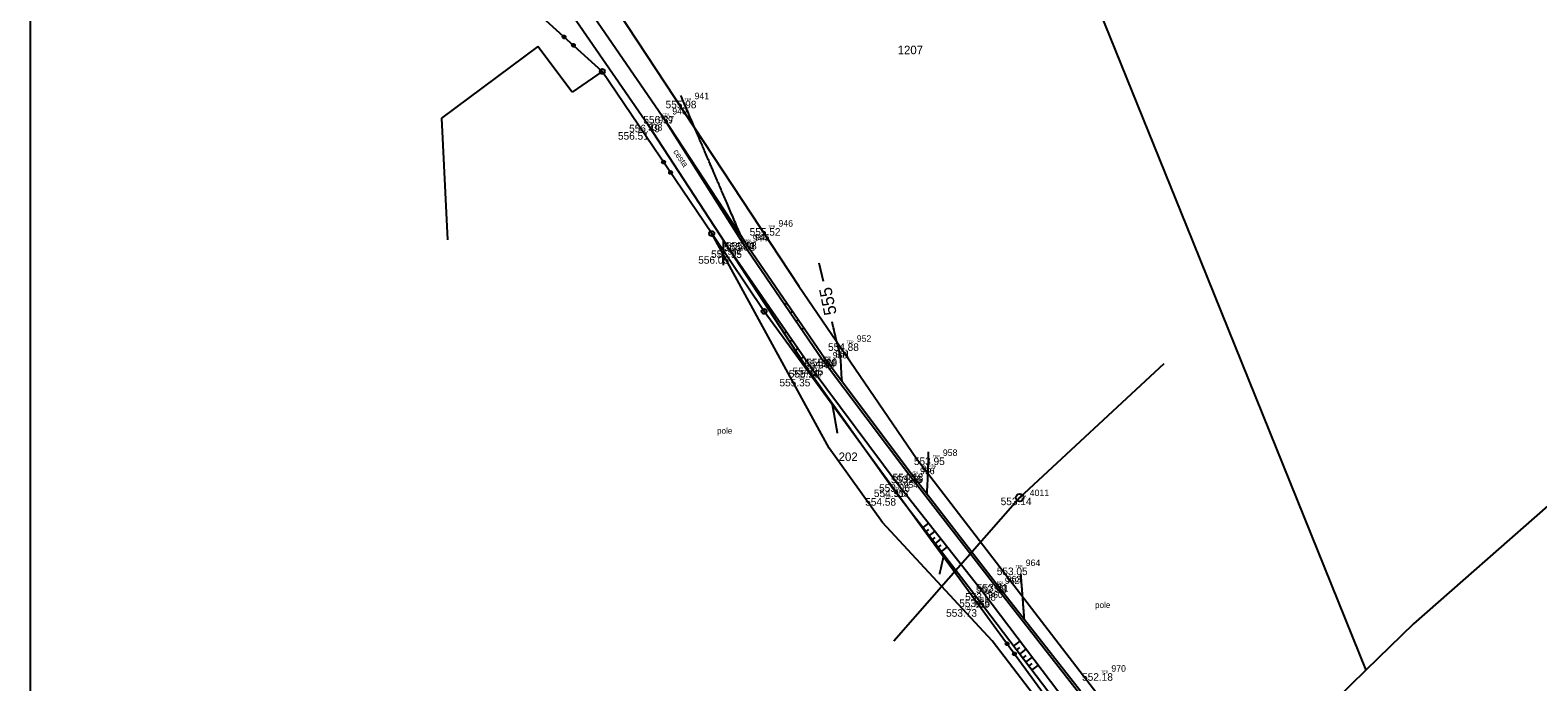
# Model space of a CAD drawing. Extents: x -604848 to -603227, y -1111879 to -1109838.
# Drawn here: x -604847.7 to -604547.7, y -1111483.6 to -1111354 of the extents above; entities that cross this region are included whole.
import ezdxf

# ---------------------------------------------------------------- set-up
doc = ezdxf.new("R2010")
doc.units = 0
for name, color, linetype in [('1', 7, 'Continuous'), ('10', 7, 'Continuous'), ('14', 7, 'Continuous'), ('18', 7, 'Continuous'), ('19', 7, 'Continuous'), ('20', 7, 'Continuous'), ('28', 7, 'Continuous'), ('4', 7, 'Continuous'), ('5', 7, 'Continuous'), ('62', 7, 'Continuous'), ('7', 7, 'Continuous'), ('8', 7, 'Continuous'), ('9', 7, 'Continuous'), ('Default', 7, 'Continuous')]:
    doc.layers.add(name, color=color, linetype=linetype)

# ---------------------------------------------------------------- blocks, each defined once
blk = doc.blocks.new('Z105')
at = {"layer": '28'}
for radius in [0.5, 0.01]:
    blk.add_circle((0, 0), radius, dxfattribs=at)
blk = doc.blocks.new('POINT_DISPLAY')
at = {"layer": 'Default'}
blk.add_line((0, 0), (0, 0), dxfattribs=at)
blk = doc.blocks.new('Z101')
at = {"layer": '28'}
for radius in [0.75, 0.01]:
    blk.add_circle((0, 0), radius, dxfattribs=at)
blk = doc.blocks.new('Z206')
at = {"layer": '62'}
for p, q in [((-1.7, 0.1), (-1.5, 0.3)), ((-1.7, -0.1), (-1.7, 0.1)), ((-1.6, 0.1), (-1.6, -0.1)), ((-1.5, 0.3), (-1.3, 0.3)), ((-1.5, -0.2), (-1.5, 0.2)), ((-1.5, 0.2), (-1.3, 0.2)), ((-1.4, 0.2), (-1.4, -0.2)), ((-1.3, 0.3), (-1.1, 0.1)), ((-1.3, 0.2), (-1.3, -0.2)), ((-1.2, -0.1), (-1.2, 0.1)), ((-1.1, 0.1), (-1.1, -0.1)), ((0.8, 0.1), (1, 0.3)), ((0.8, -0.1), (0.8, 0.1)), ((0.9, 0.1), (0.9, -0.1)), ((1, 0.3), (1.2, 0.3)), ((1, -0.2), (1, 0.2)), ((1, 0.2), (1.2, 0.2)), ((1.1, 0.2), (1.1, -0.2)), ((1.2, 0.3), (1.4, 0.1)), ((1.2, 0.2), (1.2, -0.2)), ((1.3, -0.1), (1.3, 0.1)), ((1.4, 0.1), (1.4, -0.1)), ((-1.5, -0.3), (-1.7, -0.1)), ((-1.6, -0.1), (-1.5, -0.2)), ((-1.3, -0.3), (-1.5, -0.3)), ((-1.1, -0.1), (-1.3, -0.3)), ((-1.3, -0.2), (-1.2, -0.1)), ((1, -0.3), (0.8, -0.1)), ((0.9, -0.1), (1, -0.2)), ((1.2, -0.3), (1, -0.3)), ((1.4, -0.1), (1.2, -0.3)), ((1.2, -0.2), (1.3, -0.1))]:
    blk.add_line(p, q, dxfattribs=at)

msp = doc.modelspace()

# ---------------------------------------------------------------- linework, layer by layer
at = {"layer": '1'}
for p, q in [((-604684.78, -1111226.85), (-604617.61, -1111392.95)), ((-604732.69, -1111347.27), (-604694.74, -1111404.88)), ((-604746.66, -1111357.26), (-604765.86, -1111371.5)), ((-604739.83, -1111366.3), (-604746.66, -1111357.26)), ((-604733.84, -1111362.2), (-604739.83, -1111366.3)), ((-604765.86, -1111371.5), (-604764.64, -1111395.7)), ((-604688.69, -1111437.09), (-604712.07, -1111394.44)), ((-604617.61, -1111392.95), (-604581.91, -1111481.23)), ((-604694.74, -1111404.88), (-604671.29, -1111439.17)), ((-604678.05, -1111451.87), (-604688.69, -1111437.09)), ((-604671.29, -1111439.17), (-604631.49, -1111490.96)), ((-604545.66, -1111448.58), (-604572.43, -1111472.02)), ((-604656.29, -1111475.4), (-604678.05, -1111451.87)), ((-604572.43, -1111472.02), (-604581.91, -1111481.23)), ((-604624.3, -1111517.02), (-604656.29, -1111475.4)), ((-604581.91, -1111481.23), (-604592.51, -1111491.58))]:
    msp.add_line(p, q, dxfattribs=at)
msp.add_lwpolyline([(-604253.71, -1111878.79), (-604253.71, -1111038.79), (-604847.71, -1111038.79), (-604847.71, -1111878.79), (-604253.71, -1111878.79)], dxfattribs=at)
at = {"layer": '10'}
for p, q in [((-604721.91, -1111371.06), (-604705.47, -1111396.11)), ((-604692.86, -1111421.57), (-604708.43, -1111397.78)), ((-604705.47, -1111396.11), (-604689.5, -1111419.35)), ((-604689.5, -1111419.35), (-604672.3, -1111442.2)), ((-604675.9, -1111445.34), (-604692.86, -1111421.57)), ((-604672.3, -1111442.2), (-604655.38, -1111464.11)), ((-604659.04, -1111467.21), (-604675.9, -1111445.34)), ((-604655.38, -1111464.11), (-604638.7, -1111485.39)), ((-604642.45, -1111489.02), (-604659.04, -1111467.21))]:
    msp.add_line(p, q, dxfattribs=at)
at = {"layer": '4'}
for p, q in [((-604740.23, -1111350.33), (-604724.71, -1111372.8)), ((-604737.6, -1111348.29), (-604721.91, -1111371.06)), ((-604733.84, -1111362.2), (-604745.77, -1111351.46)), ((-604712.07, -1111394.44), (-604733.84, -1111362.2)), ((-604721.91, -1111371.06), (-604705.89, -1111396.34)), ((-604708.43, -1111397.78), (-604724.71, -1111372.8)), ((-604701.64, -1111409.91), (-604712.07, -1111394.44)), ((-604692.25, -1111421.11), (-604708.43, -1111397.78)), ((-604705.89, -1111396.34), (-604689.99, -1111419.58)), ((-604639.06, -1111495.46), (-604701.64, -1111409.91)), ((-604692.25, -1111421.11), (-604674.94, -1111444.31)), ((-604672.61, -1111442.59), (-604689.99, -1111419.58)), ((-604655.73, -1111464.43), (-604672.61, -1111442.59)), ((-604674.94, -1111444.31), (-604657.89, -1111465.95)), ((-604657.89, -1111465.95), (-604641.32, -1111487.8)), ((-604639.07, -1111485.72), (-604655.73, -1111464.43))]:
    msp.add_line(p, q, dxfattribs=at)
at = {"layer": '5'}
for q in [(-604622.03, -1111420.28), (-604675.85, -1111475.52)]:
    msp.add_line((-604650.78, -1111446.95), q, dxfattribs=at)
at = {"layer": '7'}
msp.add_line((-604689.8, -1111403.97), (-604690.71, -1111400.34), dxfattribs=at)
for points, degree in [([(-604706.24, -1111394.94), (-604710.23, -1111385.62), (-604714.22, -1111376.3), (-604718.21, -1111366.99)], 2), ([(-604709.81, -1111395.67), (-604709.81, -1111397.35), (-604709.8, -1111399.04), (-604709.8, -1111400.72)], 2), ([(-604686.08, -1111423.89), (-604686.32, -1111421.73), (-604686.28, -1111419.55), (-604686.79, -1111417.41), (-604687.24, -1111415.58), (-604687.68, -1111413.8), (-604688.12, -1111411.99)], 3), ([(-604688.14, -1111428.2), (-604687.79, -1111430.18), (-604687.44, -1111432.16), (-604687.09, -1111434.14)], 2), ([(-604669.19, -1111446.22), (-604669.11, -1111444.03), (-604669.02, -1111441.84), (-604668.95, -1111439.64), (-604668.93, -1111439.04), (-604668.93, -1111438.44), (-604668.93, -1111437.83)], 3), ([(-604665.89, -1111458.33), (-604666.18, -1111459.61), (-604666.47, -1111460.89), (-604666.76, -1111462.18)], 2), ([(-604649.84, -1111471.17), (-604650.07, -1111468.17), (-604650.3, -1111465.17), (-604650.53, -1111462.16)], 2)]:
    msp.add_open_spline(points, degree=degree, dxfattribs=at)
at = {"layer": '8'}
for p, q in [((-604697.11, -1111408.27), (-604697.53, -1111408.56)), ((-604695.98, -1111409.92), (-604696.4, -1111410.21)), ((-604694.85, -1111411.57), (-604695.27, -1111411.86)), ((-604693.71, -1111413.21), (-604694.14, -1111413.51)), ((-604697.62, -1111414.3), (-604697.17, -1111414.01)), ((-604696.53, -1111415.98), (-604696.03, -1111415.66)), ((-604695.43, -1111417.65), (-604694.89, -1111417.3)), ((-604694.33, -1111419.32), (-604693.75, -1111418.94)), ((-604670.04, -1111452.94), (-604668.86, -1111452.03)), ((-604669.43, -1111453.74), (-604668.83, -1111453.28)), ((-604668.82, -1111454.53), (-604667.62, -1111453.6)), ((-604668.21, -1111455.32), (-604667.6, -1111454.85)), ((-604667.6, -1111456.11), (-604666.38, -1111455.17)), ((-604666.99, -1111456.9), (-604666.38, -1111456.43)), ((-604666.38, -1111457.7), (-604665.14, -1111456.74)), ((-604651.99, -1111476.48), (-604650.67, -1111475.47)), ((-604651.39, -1111477.27), (-604650.73, -1111476.77)), ((-604650.78, -1111478.07), (-604649.46, -1111477.07)), ((-604650.17, -1111478.86), (-604649.52, -1111478.36)), ((-604649.57, -1111479.66), (-604648.25, -1111478.66)), ((-604648.96, -1111480.46), (-604648.31, -1111479.96)), ((-604648.36, -1111481.25), (-604647.05, -1111480.25))]:
    msp.add_line(p, q, dxfattribs=at)

# ---------------------------------------------------------------- block references
at = {"layer": '18'}
for p in [(-604717.49, -1111368.03), (-604721.91, -1111371.06), (-604726.78, -1111374.27), (-604724.71, -1111372.8), (-604700.79, -1111393.36), (-604708.43, -1111397.78), (-604705.89, -1111396.34), (-604705.47, -1111396.11), (-604710.97, -1111398.94), (-604685.21, -1111416.27), (-604689.5, -1111419.35), (-604692.86, -1111421.57), (-604692.25, -1111421.11), (-604689.99, -1111419.58), (-604694.85, -1111423.33), (-604668.07, -1111438.97), (-604672.61, -1111442.59), (-604672.3, -1111442.2), (-604675.9, -1111445.34), (-604674.94, -1111444.31), (-604677.82, -1111447.05), (-604650.78, -1111446.95), (-604651.58, -1111460.86), (-604655.38, -1111464.11), (-604659.04, -1111467.21), (-604657.89, -1111465.95), (-604655.73, -1111464.43), (-604661.68, -1111469.14), (-604634.54, -1111481.87)]:
    msp.add_blockref('POINT_DISPLAY', p, dxfattribs=at)
at = {"layer": '28'}
for p in [(-604733.84, -1111362.2), (-604712.07, -1111394.44), (-604701.64, -1111409.91)]:
    msp.add_blockref('Z105', p, dxfattribs=at)
at = {"layer": '4'}
for p, xscale, yscale, rotation in [((-604740.64, -1111356.08), 0.9999965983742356, 0.9999965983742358, 138.00465658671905), ((-604721.05, -1111381.14), 0.9999995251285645, 0.9999995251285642, 124.0291299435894), ((-604652.64, -1111476.9), 0.9999977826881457, 0.9999977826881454, 126.18541902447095)]:
    msp.add_blockref('Z206', p, dxfattribs=dict(at, xscale=xscale, yscale=yscale, rotation=rotation))
at = {"layer": '5'}
msp.add_blockref('Z101', (-604650.78, -1111446.95), dxfattribs=at)

# ---------------------------------------------------------------- texts
at = {"layer": '14'}
for s, p in [('1207', (-604675.07, -1111358.78)), ('202', (-604686.81, -1111439.68))]:
    msp.add_text(s, height=1.7, dxfattribs=at).set_placement(p)
at = {"layer": '18'}
for s, p in [('TER', (-604717.49, -1111368.03)), ('CES', (-604721.91, -1111371.06)), ('TER', (-604726.78, -1111374.27)), ('CES', (-604724.71, -1111372.8)), ('TER', (-604700.79, -1111393.36)), ('CES', (-604708.43, -1111397.78)), ('CES', (-604705.89, -1111396.34)), ('POL', (-604705.47, -1111396.11)), ('TER', (-604710.97, -1111398.94)), ('TER', (-604685.21, -1111416.27)), ('CES', (-604689.99, -1111419.58)), ('POL', (-604689.5, -1111419.35)), ('POL', (-604692.86, -1111421.57)), ('CES', (-604692.25, -1111421.11)), ('TER', (-604694.85, -1111423.33)), ('TER', (-604668.07, -1111438.97)), ('CES', (-604672.61, -1111442.59)), ('POL', (-604672.3, -1111442.2)), ('POL', (-604675.9, -1111445.34)), ('CES', (-604674.94, -1111444.31)), ('TER', (-604677.82, -1111447.05)), ('STA', (-604650.78, -1111446.95)), ('TER', (-604651.58, -1111460.86)), ('CES', (-604655.73, -1111464.43)), ('POL', (-604655.38, -1111464.11)), ('POL', (-604659.04, -1111467.21)), ('CES', (-604657.89, -1111465.95)), ('TER', (-604661.68, -1111469.14)), ('TER', (-604634.54, -1111481.87))]:
    msp.add_text(s, height=0.5, dxfattribs=at).set_placement(p)
at = {"layer": '19'}
for s, p in [('941', (-604715.49, -1111367.73)), ('939', (-604722.71, -1111372.5)), ('940', (-604719.91, -1111370.76)), ('938', (-604724.78, -1111373.97)), ('946', (-604698.79, -1111393.06)), ('944', (-604703.89, -1111396.04)), ('945', (-604703.47, -1111395.81)), ('942', (-604708.97, -1111398.64)), ('943', (-604706.43, -1111397.48)), ('952', (-604683.21, -1111415.97)), ('950', (-604687.99, -1111419.28)), ('951', (-604687.5, -1111419.05)), ('947', (-604692.85, -1111423.03)), ('948', (-604690.86, -1111421.27)), ('949', (-604690.25, -1111420.81)), ('958', (-604666.07, -1111438.67)), ('955', (-604672.94, -1111444.01)), ('956', (-604670.61, -1111442.29)), ('957', (-604670.3, -1111441.9)), ('953', (-604675.82, -1111446.75)), ('954', (-604673.9, -1111445.04)), ('4011', (-604648.78, -1111446.65)), ('964', (-604649.58, -1111460.56)), ('961', (-604655.89, -1111465.65)), ('962', (-604653.73, -1111464.13)), ('963', (-604653.38, -1111463.81)), ('960', (-604657.04, -1111466.91)), ('959', (-604659.68, -1111468.84)), ('970', (-604632.54, -1111481.57))]:
    msp.add_text(s, height=1.3, dxfattribs=at).set_placement(p)
at = {"layer": '20'}
for s, p in [('555.98 ', (-604721.25, -1111369.53)), ('556.37 ', (-604725.68, -1111372.56)), ('556.51 ', (-604730.73, -1111375.77)), ('556.49 ', (-604728.51, -1111374.3)), ('555.52 ', (-604704.52, -1111394.86)), ('555.95 ', (-604712.2, -1111399.28)), ('555.82 ', (-604709.62, -1111397.84)), ('555.98 ', (-604709.24, -1111397.61)), ('556.05 ', (-604714.76, -1111400.44)), ('554.88 ', (-604688.92, -1111417.77)), ('555.20 ', (-604693.25, -1111420.85)), ('555.19 ', (-604696.74, -1111423.07)), ('554.95 ', (-604695.99, -1111422.61)), ('554.84 ', (-604693.66, -1111421.08)), ('555.35 ', (-604698.58, -1111424.83)), ('553.95 ', (-604671.83, -1111440.47)), ('553.86 ', (-604676.4, -1111444.09)), ('554.18 ', (-604676.1, -1111443.7)), ('554.51 ', (-604679.8, -1111446.84)), ('553.96 ', (-604678.76, -1111445.81)), ('554.58 ', (-604681.53, -1111448.55)), ('553.14 ', (-604654.56, -1111448.45)), ('553.05 ', (-604655.34, -1111462.36)), ('552.98 ', (-604659.5, -1111465.93)), ('553.21 ', (-604659.29, -1111465.61)), ('553.65 ', (-604662.81, -1111468.71)), ('553.08 ', (-604661.64, -1111467.45)), ('553.73 ', (-604665.42, -1111470.64)), ('552.18 ', (-604638.36, -1111483.37))]:
    msp.add_text(s, height=1.5, dxfattribs=at).set_placement(p)
at = {"layer": '7'}
msp.add_text('555', height=2.5, rotation=101.7, dxfattribs=at).set_placement((-604687.17, -1111410.39))
at = {"layer": '9'}
msp.add_text('cesta', height=1.2, rotation=304.2, dxfattribs=at).set_placement((-604719.8, -1111378.19))
for p in [(-604711.01, -1111434.25), (-604635.78, -1111468.9)]:
    msp.add_text('pole', height=1.2, dxfattribs=at).set_placement(p)

doc.saveas('drawing.dxf')
